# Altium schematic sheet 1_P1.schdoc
size 431 x 309 mm
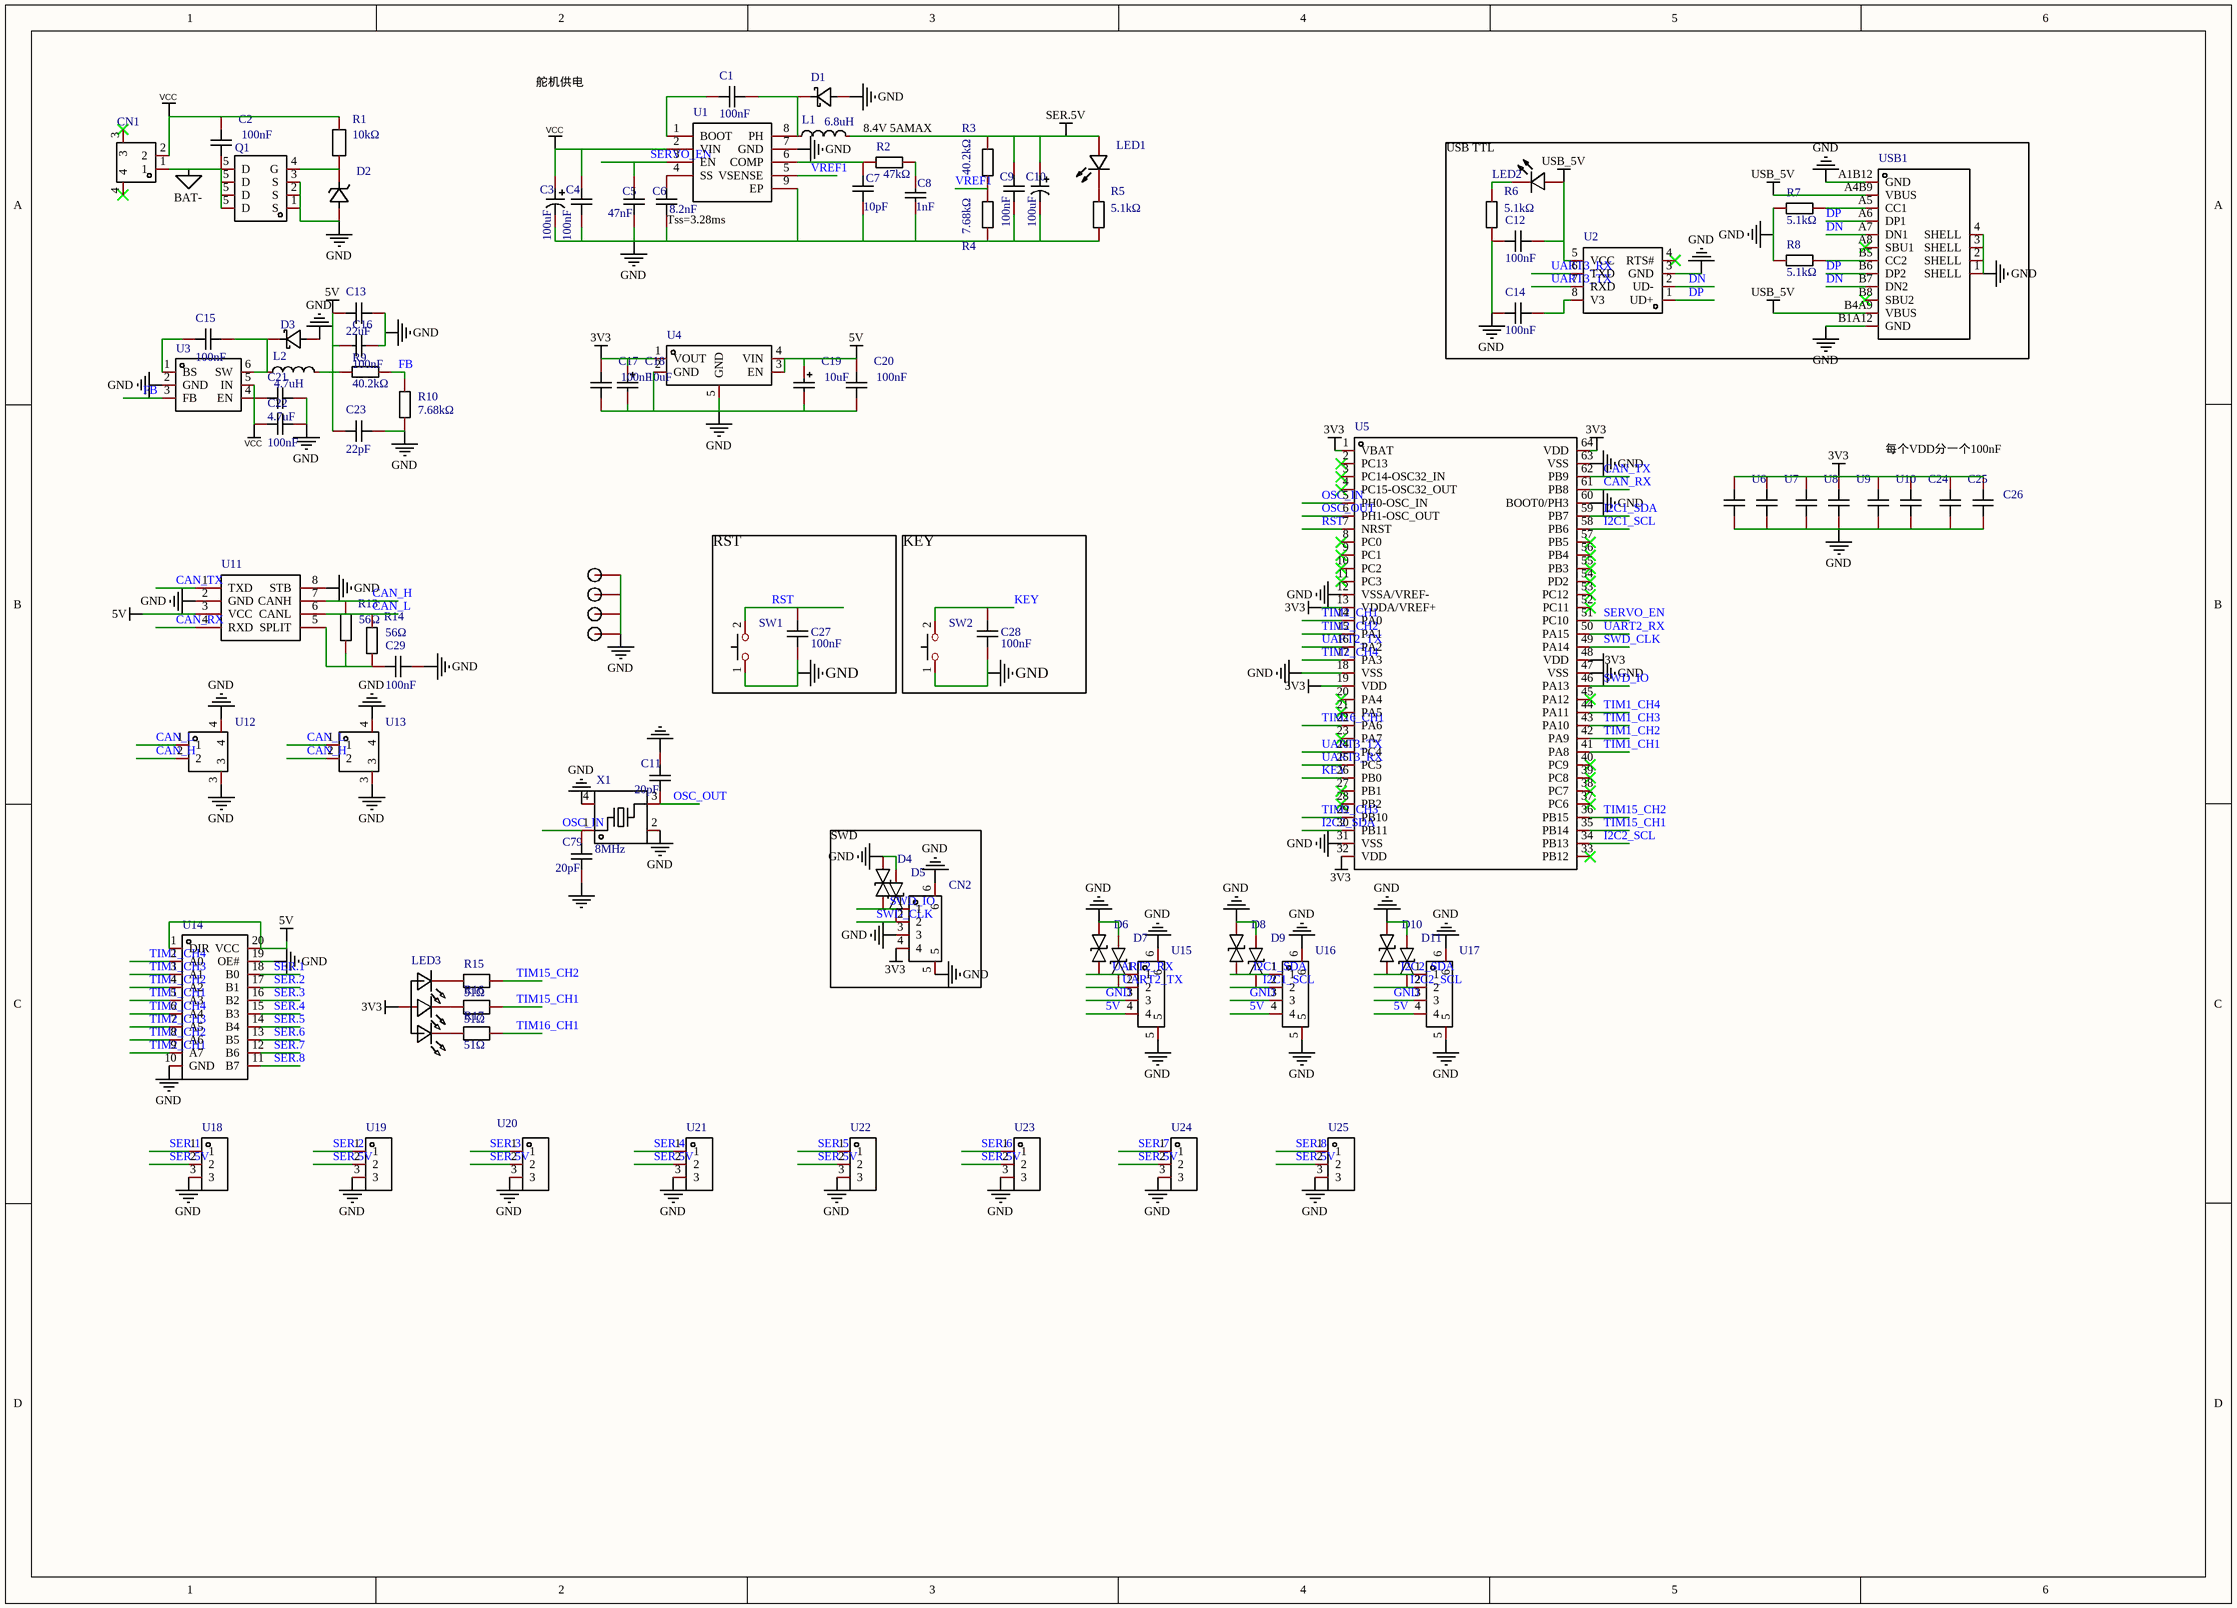
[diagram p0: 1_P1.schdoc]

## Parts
C1  value 100nF  [C0603]  (hidden comment: CC0603KRX7R9BB104)
C2  value 100nF  [C0603]  (hidden comment: CL10B104KC8NNNC)
C3  value 100uF  [CAP-SMD_BD6.3-L6.6-W6.6-LS7.2-FD]  (hidden comment: VT1E101M-CRE54)
C4  value 100nF  [C0603]  (hidden comment: CC0603KRX7R9BB104)
C5  value 47nF  [C0603]  (hidden comment: CL10B104KC8NNNC)
C6  value 8.2nF  [C0603]  (hidden comment: 0603B822J500CT)
C7  value 10pF  [C0603]  (hidden comment: CC0603GRNPO9BN100)
C8  value 1nF  [C0603]  (hidden comment: CL10B102KB8NNNC)
C9  value 100nF  [C0603]  (hidden comment: CC0603KRX7R9BB104)
C10  value 100uF  [CAP-SMD_BD6.3-L6.6-W6.6-LS7.2-FD]  (hidden comment: VT1E101M-CRE54)
C11  value 20pF  [C0603]  (hidden comment: 0603CG200G500NT)
C12  value 100nF  [C0603]  (hidden comment: TCC0603X7R104K500CT)
C13  value 22uF  [C0603]  (hidden comment: GRT188C80J226ME13D)
C14  value 100nF  [C0603]  (hidden comment: TCC0603X7R104K500CT)
C15  value 100nF  [C0603]  (hidden comment: CL10B104KC8NNNC)
C16  value 100nF  [C0402]  (hidden comment: GRM155R71E104KE14D)
C17  value 100nF  [C0402]  (hidden comment: CGA2B3X7R1V104MT0Y0F)
C18  value 10uF  [CAP-SMD_L3.5-W2.8-R-RD]  (hidden comment: TC211B106K025Y)
C19  value 10uF  [CAP-SMD_L3.5-W2.8-R-RD]  (hidden comment: TC211B106K025Y)
C20  value 100nF  [C0402]  (hidden comment: CGA2B3X7R1V104MT0Y0F)
C21  value 4.7uF  [C0603]  (hidden comment: GRM188C81E475KE11D)
C22  value 100nF  [C0603]  (hidden comment: CL10B104KC8NNNC)
C23  value 22pF  [C0603]  (hidden comment: GCM1885C2A220JA16D)
C24  0603  [C0603]  (value not drawn)
C25  0603  [C0603]  (value not drawn)
C26  0603  [C0603]  (value not drawn)
C27  Name: 100nF  [C0603]  (hidden comment: 1uF)
C28  Name: 100nF  [C0603]  (hidden comment: 1uF)
C29  value 100nF  [C0603]  (hidden comment: CL10B104KC8NNNC)
C79  value 20pF  [C0603]  (hidden comment: 0603CG200G500NT)
CN1  XT30PW-M  [CONN-TH_XT30PW-M]  (value not drawn)
CN2  X9821WVS-04-9TSN  [CONN-SMD_4P-P1.25_X9821WVS-04-9TSN]  (value not drawn)
D1  DSK310  [SOD-123_L2.7-W1.8-LS3.7-RD]  (value not drawn)
D2  ZMM9V1  [LL-34_L3.5-W1.5-RD]  (value not drawn)
D3  DSK310  [SOD-123_L2.7-W1.8-LS3.7-RD]  (value not drawn)
D4  PESD5V0L1BA  [SOD-323_L1.7-W1.3-LS2.5-BI]  (value not drawn)
D5  PESD5V0L1BA  [SOD-323_L1.7-W1.3-LS2.5-BI]  (value not drawn)
D6  PESD5V0L1BA  [SOD-323_L1.7-W1.3-LS2.5-BI]  (value not drawn)
D7  PESD5V0L1BA  [SOD-323_L1.7-W1.3-LS2.5-BI]  (value not drawn)
D8  PESD5V0L1BA  [SOD-323_L1.7-W1.3-LS2.5-BI]  (value not drawn)
D9  PESD5V0L1BA  [SOD-323_L1.7-W1.3-LS2.5-BI]  (value not drawn)
D10  PESD5V0L1BA  [SOD-323_L1.7-W1.3-LS2.5-BI]  (value not drawn)
D11  PESD5V0L1BA  [SOD-323_L1.7-W1.3-LS2.5-BI]  (value not drawn)
H1  M2.5_M2.5  [M2.5]  (value not drawn)
H2  M2.5_M2.5  [M2.5]  (value not drawn)
H3  M2.5_M2.5  [M2.5]  (value not drawn)
H4  M2.5_M2.5  [M2.5]  (value not drawn)
L1  value 6.8uH  [IND-SMD_L6.6-W6.6]  (hidden comment: SMMS0630-6R8M)
L2  value 4.7uH  [IND-SMD_L4.5-W4.0-1]  (hidden comment: MCS0420-4R7MPN2)
LED1  NCD0805R1  [LED0805-RD_RED]  (value not drawn)
LED2  NCD0805R1  [LED0805-RD_RED]  (value not drawn)
LED3  HL-PCF-3216S39FU70GH203BC-A  [LED-SMD_4P-L3.2-W1.5-BL]  (value not drawn)
Q1  WSD3066DN33  [DFN-8_L3.3-W3.3-P0.65-BL]  (value not drawn)
R1  value 10kΩ  [R0603]  (hidden comment: AR03BTD1002)
R2  value 47kΩ  [R0603]  (hidden comment: RS-03K473JT)
R3  value 40.2kΩ  [R0603]  (hidden comment: TC0325B4022T5E)
R4  value 7.68kΩ  [R0603]  (hidden comment: RMC06037.68K1%N)
R5  value 5.1kΩ  [R0603]  (hidden comment: RMC06035.1K1%N)
R6  value 5.1kΩ  [R0603]  (hidden comment: RMC06035.1K5%N)
R7  value 5.1kΩ  [R0603]  (hidden comment: RMC06035.1K1%N)
R8  value 5.1kΩ  [R0603]  (hidden comment: RMC06035.1K1%N)
R9  value 40.2kΩ  [R0603]  (hidden comment: TC0325B4022T5E)
R10  value 7.68kΩ  [R0603]  (hidden comment: RMC06037.68K1%N)
R13  value 56Ω  [R0603]  (hidden comment: CR0603JA0560G)
R14  value 56Ω  [R0603]  (hidden comment: CR0603JA0560G)
R15  value 51Ω  [R0603]  (hidden comment: ACPP0603 51R B)
R16  value 51Ω  [R0603]  (hidden comment: ACPP0603 51R B)
R17  value 51Ω  [R0603]  (hidden comment: ACPP0603 51R B)
SW1  YD-3410  [SW-SMD_L3.9-W2.9-LS4.8-EH-A]  (value not drawn)
SW2  YD-3410  [SW-SMD_L3.9-W2.9-LS4.8-EH-A]  (value not drawn)
U1  TPS54531DDAR  [SOIC-8_L5.0-W4.0-P1.27-LS6.0-BL-EP2.0]  (value not drawn)
U2  CH340N  [SOP-8_L4.9-W3.9-P1.27-LS6.0-BL]  (value not drawn)
U3  RY8411  [SOT-23-6_L2.9-W1.6-P0.95-LS2.8-TL]  (value not drawn)
U4  SK6019AD4-33  [XDFN-4_L1.0-W1.0-P0.65-BL-EP]  (value not drawn)
U5  STM32L431RCT6  [LQFP-64_L10.0-W10.0-P0.50-LS12.0-BL]  (value not drawn)
U6  CAP,MLCC,X7R,100nF,10V,10%,SMD0402,ROHS  [C0402]  (value not drawn)
U7  CAP,MLCC,X7R,100nF,10V,10%,SMD0402,ROHS  [C0402]  (value not drawn)
U8  CAP,MLCC,X7R,100nF,10V,10%,SMD0402,ROHS  [C0402]  (value not drawn)
U9  CAP,MLCC,X7R,100nF,10V,10%,SMD0402,ROHS  [C0402]  (value not drawn)
U10  CAP,MLCC,X7R,100nF,10V,10%,SMD0402,ROHS  [C0402]  (value not drawn)
U11  TJA1040T/CM,118  [SOIC-8_L5.0-W4.0-P1.27-LS6.0-BL]  (value not drawn)
U12  1.25-2PWTDK  [CONN-SMD_2P-P1.25_SHOU_1.25-2PWTDK]  (value not drawn)
U13  1.25-2PWTDK  [CONN-SMD_2P-P1.25_SHOU_1.25-2PWTDK]  (value not drawn)
U14  74HC245PW  [TSSOP-20_L6.5-W4.4-P0.65-LS6.4-BL]  (value not drawn)
U15  1.25-4PWTDK  [CONN-SMD_4P-P1.25_SHOUHAN_1.25-4PWTDK]  (value not drawn)
U16  1.25-4PWTDK  [CONN-SMD_4P-P1.25_SHOUHAN_1.25-4PWTDK]  (value not drawn)
U17  1.25-4PWTDK  [CONN-SMD_4P-P1.25_SHOUHAN_1.25-4PWTDK]  (value not drawn)
U18  3pin插件排针  [HDR-TH_3P-P2.00-V-M]  (value not drawn)
U19  3pin插件排针  [HDR-TH_3P-P2.00-V-M]  (value not drawn)
U20  3pin插件排针  [HDR-TH_3P-P2.00-V-M]  (value not drawn)
U21  3pin插件排针  [HDR-TH_3P-P2.00-V-M]  (value not drawn)
U22  3pin插件排针  [HDR-TH_3P-P2.00-V-M]  (value not drawn)
U23  3pin插件排针  [HDR-TH_3P-P2.00-V-M]  (value not drawn)
U24  3pin插件排针  [HDR-TH_3P-P2.00-V-M]  (value not drawn)
U25  3pin插件排针  [HDR-TH_3P-P2.00-V-M]  (value not drawn)
USB1  TYPE-C 16PIN 3MD(385)  [USB-C-SMD_TYPE-C16PIN]  (value not drawn)
X1  value 8MHz  [OSC-SMD_4P-L3.2-W2.5-BL]  (hidden comment: X32258MOB4SI)

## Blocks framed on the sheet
USB TTL: C12 C14 LED2 R6-R8 U2 USB1
RST: C27 SW1
KEY: C28 SW2
SWD: CN2 D4 D5

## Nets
3V3: C17.2 C18.1 C24.2 C25.2 C26.2 CN2.4 LED3.2 U4.1(VOUT) U5.1(VBAT) U5.13(VDDA/VREF+) U5.19(VDD) U5.32(VDD) U5.48(VDD) U5.64(VDD) U6.2 U7.2 U8.2 U9.2 U10.2
5V: C13.1 C16.1 C19.1 C20.2 C23.1 L2.2 R9.2 U4.3(EN) U4.4(VIN) U11.3(VCC) U14.1(DIR) U14.20(VCC) U15.4 U16.4 U17.4
BAT-: C2.1 CN1.1 Q1.5(D)
GND: C3.2 C4.1 C5.1 C6.1 C7.1 C8.1 C9.1 C10.2 C11.1 C12.1 C13.2 C14.1 C16.2 C17.1 C18.2 C19.2 C20.1 C21.2 C22.2 C23.2 C24.1 C25.1 C26.1 C27.1 C28.1 C29.2 C79.2 CN2.3 CN2.5 CN2.6 D1.2(A) D2.2(A) D3.2(A) D4.2 D5.2 D6.2 D7.2 D8.2 D9.2 D10.2 D11.2 H1.1 H2.1 H3.1 H4.1 Q1.1(S) Q1.2(S) Q1.3(S) R4.1 R5.1 R6.1 R7.1 R8.1 R10.1 SW1.1 SW2.1 U1.7(GND) U1.9(EP) U2.3(GND) U3.2(GND) U4.2(GND) U4.5(GND) U5.12(VSSA/VREF-) U5.18(VSS) U5.31(VSS) U5.47(VSS) U5.60(BOOT0/PH3) U5.63(VSS) U6.1 U7.1 U8.1 U9.1 U10.1 U11.2(GND) U11.8(STB) U12.3 U12.4 U13.3 U13.4 U14.10(GND) U14.19(OE#) U15.3 U15.5 U15.6 U16.3 U16.5 U16.6 U17.3 U17.5 U17.6 U18.3 U19.3 U20.3 U21.3 U22.3 U23.3 U24.3 U25.3 USB1.1(SHELL) USB1.2(SHELL) USB1.3(SHELL) USB1.4(SHELL) USB1.A1B12(GND) USB1.B1A12(GND) X1.2(GND) X1.4(GND)
SER.5V: C9.2 C10.1 L1.2 LED1.2(+) R3.2 U18.2 U19.2 U20.2 U21.2 U22.2 U23.2 U24.2 U25.2
USB_5V: C12.2 LED2.2(+) U2.5(VCC) USB1.A4B9(VBUS) USB1.B4A9(VBUS)
VCC: C2.2 C3.1 C4.2 C21.1 C22.1 CN1.2 R1.2 U1.2(VIN) U3.4(EN) U3.5(IN)
CAN_H: R13.2 U11.7(CANH) U12.2 U13.2
CAN_L: R14.2 U11.6(CANL) U12.1 U13.1
CAN_RX: U5.61(PB8) U11.4(RXD)
CAN_TX: U5.62(PB9) U11.1(TXD)
DN: U2.2(UD-) USB1.A7(DN1) USB1.B7(DN2)
DP: U2.1(UD+) USB1.A6(DP1) USB1.B6(DP2)
FB: R9.1 R10.2 U3.3(FB)
I2C1_SCL: D9.1 U5.58(PB6) U16.2
I2C1_SDA: D8.1 U5.59(PB7) U16.1
I2C2_SCL: D11.1 U5.34(PB13) U17.2
I2C2_SDA: D10.1 U5.30(PB11) U17.1
KEY: C28.2 SW2.2 U5.26(PB0)
OSC_IN: C79.1 U5.5(PH0-OSC_IN) X1.1
OSC_OUT: C11.2 U5.6(PH1-OSC_OUT) X1.3
RST: C27.2 SW1.2 U5.7(NRST)
SER.1: U14.18(B0) U18.1
SER.2: U14.17(B1) U19.1
SER.3: U14.16(B2) U20.1
SER.4: U14.15(B3) U21.1
SER.5: U14.14(B4) U22.1
SER.6: U14.13(B5) U23.1
SER.7: U14.12(B6) U24.1
SER.8: U14.11(B7) U25.1
SERVO_EN: C5.2 U1.3(EN) U5.51(PC10)
SWD_CLK: CN2.2 D5.1 U5.49(PA14)
SWD_IO: CN2.1 D4.1 U5.46(PA13)
TIM1_CH1: U5.41(PA8) U14.5(A3)
TIM1_CH2: U5.42(PA9) U14.4(A2)
TIM1_CH3: U5.43(PA10) U14.3(A1)
TIM1_CH4: U5.44(PA11) U14.2(A0)
TIM2_CH1: U5.14(PA0) U14.9(A7)
TIM2_CH2: U5.15(PA1) U14.8(A6)
TIM2_CH3: U5.29(PB10) U14.7(A5)
TIM2_CH4: U5.17(PA3) U14.6(A4)
TIM15_CH1: R16.2 U5.35(PB14)
TIM15_CH2: R15.2 U5.36(PB15)
TIM16_CH1: R17.2 U5.22(PA6)
UART2_RX: D6.1 U5.50(PA15) U15.1
UART2_TX: D7.1 U5.16(PA2) U15.2
UART3_RX: U2.6(TXD) U5.25(PC5)
UART3_TX: U2.7(RXD) U5.24(PC4)
VREF1: R3.1 R4.2 U1.5(VSENSE)
NetC1_1: C1.1 U1.1(BOOT)
NetC1_2: C1.2 D1.1(K) L1.1 U1.8(PH)
NetC6_2: C6.2 U1.4(SS)
NetC7_2: C7.2 R2.1 U1.6(COMP)
NetC8_2: C8.2 R2.2
NetC14_2: C14.2 U2.8(V3)
NetC15_1: C15.1 U3.1(BS)
NetC15_2: C15.2 D3.1(K) L2.1 U3.6(SW)
NetC29_1: C29.1 R13.1 R14.1 U11.5(SPLIT)
NetD2_1: D2.1(K) Q1.4(G) R1.1
NetLED1_1: LED1.1(-) R5.2
NetLED2_1: LED2.1(-) R6.2
NetLED3_1: LED3.1 R15.1
NetLED3_3: LED3.3 R16.1
NetLED3_4: LED3.4 R17.1
NetR7_2: R7.2 USB1.A5(CC1)
NetR8_2: R8.2 USB1.B5(CC2)

Not connected (* = marked no-connect by the designer): CN1 3* 4*; U2 4(RTS#)*; U5 2(PC13)* 3(PC14-OSC32_IN)* 4(PC15-OSC32_OUT)* 8(PC0)* 9(PC1)* 10(PC2)* 11(PC3)* 20(PA4)* 21(PA5)* 23(PA7)* 27(PB1)* 28(PB2)* 33(PB12)* 37(PC6)* 38(PC7)* 39(PC8)* 40(PC9)* 45(PA12)* 52(PC11)* 53(PC12)* 54(PD2)* 55(PB3)* 56(PB4)* 57(PB5)*; USB1 A8(SBU1)* B8(SBU2)*

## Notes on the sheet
- 舵机供电
- 8.4V 5AMAX
- (near C6) Tss=3.28ms
- 每个VDD分一个100nF

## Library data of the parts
C1 C4 C9 = CC0603KRX7R9BB104: 容值:100nF;精度:±10%;额定电压:50V;温度系数:X7R;; Manufacturer: YAGEO(国巨); Add into BOM: yes; Tolerance: ±10%; Voltage Rated: 50V; Temperature Coefficient: X7R
C2 C5 C15 C22 C29 = CL10B104KC8NNNC: 容值:100nF;精度:±10%;额定电压:100V;温度系数:X7R;; Manufacturer: SAMSUNG(三星); Add into BOM: yes; Tolerance: ±10%; Voltage Rated: 100V; Temperature Coefficient: X7R
C3 C10 = VT1E101M-CRE54: 容值:100uF;精度:-;额定电压:25V;; Manufacturer: VT(首科); Add into BOM: yes; Rated Voltage: 25V
C6 = 0603B822J500CT: 容值:8.2nF;精度:±5%;额定电压:50V;温度系数:X7R;; Manufacturer: 华新科(Walsin); Add into BOM: yes; Tolerance: ±5%; Voltage Rated: 50V; Temperature Coefficient: X7R
C7 = CC0603GRNPO9BN100: 容值:10pF;精度:±2%;额定电压:50V;温度系数:NP0;; Manufacturer: YAGEO(国巨); Add into BOM: yes; Tolerance: ±2%; Voltage Rated: 50V; Temperature Coefficient: NP0
C8 = CL10B102KB8NNNC: 容值:1nF;精度:±10%;额定电压:50V;温度系数:X7R;; Manufacturer: SAMSUNG(三星); Add into BOM: yes; Tolerance: ±10%; Voltage Rated: 50V; Temperature Coefficient: X7R
C11 C79 = 0603CG200G500NT: 容值:20pF;精度:±2%;额定电压:50V;温度系数:C0G;; Manufacturer: FH(风华); Add into BOM: yes; Tolerance: ±2%; Voltage Rated: 50V; Temperature Coefficient: C0G
C12 C14 = TCC0603X7R104K500CT: 容值:100nF;精度:±10%;额定电压:50V;温度系数:X7R;; Manufacturer: CCTC(三环); Add into BOM: yes; Tolerance: ±10%; Voltage Rated: 50V; Temperature Coefficient: X7R
C13 = GRT188C80J226ME13D: 容值:22uF;精度:±20%;额定电压:-;温度系数:-;; Manufacturer: muRata(村田); Add into BOM: yes; Tolerance: ±20%
C16 = GRM155R71E104KE14D: 容值:100nF;精度:±10%;额定电压:25V;温度系数:X7R;; Manufacturer: muRata(村田); Add into BOM: yes; Tolerance: ±10%; Voltage Rated: 25V; Temperature Coefficient: X7R
C17 C20 = CGA2B3X7R1V104MT0Y0F: 容值:100nF;精度:±20%;额定电压:35V;温度系数:X7R;; Manufacturer: TDK; Add into BOM: yes; Tolerance: ±20%; Voltage Rated: 35V; Temperature Coefficient: X7R
C18 C19 = TC211B106K025Y: 容值:10uF;精度:±10%;额定电压:25V;等效串联电阻:3Ω@100kHz;工作温度:-55~+125;; Manufacturer: Sunlord(顺络); Add into BOM: yes; Tolerance: ±10%; Rated Voltage: 25V
C21 = GRM188C81E475KE11D: 容值:4.7uF;精度:±10%;额定电压:-;温度系数:-;; Manufacturer: muRata(村田); Add into BOM: yes; Tolerance: ±10%
C23 = GCM1885C2A220JA16D: 容值:22pF;精度:±5%;额定电压:100V;温度系数:C0G;; Manufacturer: muRata(村田); Add into BOM: yes; Tolerance: ±5%; Voltage Rated: 100V; Temperature Coefficient: C0G
C24-C26 = 0603: Symbol: 0603_C9900021180; Add into BOM: yes
C27 C28 = 1uF: Manufacturer: YAGEO; Manufacturer Part: CC0603JRNPO0BN200; Convert to PCB: yes
CN1 = XT30PW-M: Socket,DCsupply,XT30,male,PIN:2; Manufacturer: AMASS(艾迈斯); Add into BOM: yes
CN2 = X9821WVS-04-9TSN: 参考系列:-;间距:1.25mm;插针结构:1x4P;排数:1;每排PIN数:4;行距:-;安装方式:-;触头材质:黄铜;; Manufacturer: XKB Connectivity(中国星坤); Add into BOM: yes; Pitch: 1.25mm; Pins Structure: 1x4P; Number of PINs Per Row: 4
D1 D3 = DSK310: 二极管配置:-;直流反向耐压(Vr):100V;平均整流电流(Io):3A;正向压降(Vf):850mV@3A;反向电流(Ir):500A@100V;; Manufacturer: LGE(鲁光); Symbol: DSK310_C713648; Add into BOM: yes; Reverse Voltage (Vr): 100V; Average Rectified Current (Io): 3A
D2 = ZMM9V1: 稳压值(标称值):-;精度:-;功率:500mW;反向电流(Ir):100nA@6.8V;; Manufacturer: Slkor(萨科微); Symbol: ZMM9V1_C707200; Add into BOM: yes; Power Dissipation: 500mW
D4-D11 = PESD5V0L1BA: 极性:-;反向关断电压（典型值）:-;击穿电压（最小值）:-;箝位电压:-;峰值脉冲电流（10/1000us）:-;; Manufacturer: TECH PUBLIC(台舟); Symbol: PESD5V0L1BA_C2827691; Add into BOM: yes
H1-H4 = M2.5_M2.5: Convert to PCB: yes
L1 = SMMS0630-6R8M: 电感值:6.8uH;精度:±20%;额定电流:-;直流电阻(DCR):-;; Manufacturer: SXN(顺翔诺); Add into BOM: yes; Tolerance: ±20%
L2 = MCS0420-4R7MPN2: 电感值:4.7uH;精度:±20%;额定电流:2.2A;饱和电流(Isat):3.5A;直流电阻(DCR):98mΩ;; Manufacturer: PSA(信昌电陶); Add into BOM: yes; Tolerance: ±20%; Rated Current: 2.2A; Saturation Current (Isat): 3.5A; DC Resistance (DCR): 98mΩ
LED1 LED2 = NCD0805R1: 发光颜色:红灯;; Manufacturer: 国星光电; Symbol: FC-2012HRK-620D; Add into BOM: yes; Emitted Color: 红灯
LED3 = HL-PCF-3216S39FU70GH203BC-A: 发光颜色:RGB三色;透镜颜色:无色透明;主波长:-;色温:-;光通量(25时):-;测试电流:20mA;正向电压(VF):2.4V；3.4V；3.4V;发光强度:350mcd；1000mcd；220mcd;功率:102mW；102mW；72mW;发光角度:140°;安装方式:正贴;工作温度:-40~+85;; Manufacturer: HONGLITRONIC(鸿利光电); Add into BOM: yes; Emitted Color: RGB三色; Lens Color: 无色透明; Forward Current: 20mA; Viewing Angle: 140°; Mounting Sytle: 正贴
Q1 = WSD3066DN33: 类型:N沟道;漏源电压(Vdss):30V;连续漏极电流(Id):50A;功率(Pd):45W;导通电阻(RDS(on)@Vgs,Id):5.7mΩ@10V,35A;阈值电压(Vgs(th)@Id):2.5V@250A;; Manufacturer: WINSOK微硕; Add into BOM: yes; Type: N沟道; Drain Source Voltage (Vdss): 30V; Continuous Drain Current (Id): 50A; Power Dissipation (Pd): 45W
R1 = AR03BTD1002: 阻值:10kΩ;精度:±0.01%;功率:-;温度系数:±50ppm/;最大工作电压:50V;工作温度范围:-55~+125;; Manufacturer: Viking(光颉); Add into BOM: yes; Tolerance: ±0.01%; Temperature Coefficient: ±50ppm/; Overload Voltage (Max): 50V
R2 = RS-03K473JT: 阻值:47kΩ;精度:±5%;功率:100mW;温度系数:±100ppm/;最大工作电压:50V;工作温度范围:-55~+155;; Manufacturer: FH(风华); Add into BOM: yes; Tolerance: ±5%; Power(Watts): 100mW; Overload Voltage (Max): 50V
R3 R9 = TC0325B4022T5E: 阻值:40.2kΩ;精度:±0.1%;功率:1/6W;温度系数:±25ppm/;最大工作电压:75V;工作温度范围:-55~+155;; Manufacturer: UNI-ROYAL(厚声); Add into BOM: yes; Tolerance: ±0.1%; Power(Watts): 1/6W; Temperature Coefficient: ±25ppm/; Overload Voltage (Max): 75V
R4 R10 = RMC06037.68K1%N: 阻值:7.68kΩ;精度:±1%;功率:0.1W;; Manufacturer: Tyohm(幸亚电阻); Add into BOM: yes; Tolerance: ±1%; Power(Watts): 0.1W
R5 R7 R8 = RMC06035.1K1%N: 阻值:5.1kΩ;精度:±1%;功率:0.1W;; Manufacturer: Tyohm(幸亚电阻); Add into BOM: yes; Tolerance: ±1%; Power(Watts): 0.1W
R6 = RMC06035.1K5%N: 阻值:5.1kΩ;精度:±5%;功率:0.1W;; Manufacturer: Tyohm(幸亚电阻); Add into BOM: yes; Tolerance: ±5%; Power(Watts): 0.1W
R13 R14 = CR0603JA0560G: 电阻类型:厚膜电阻;阻值:56Ω;精度:±5%;功率:1/10W;温度系数:±200ppm/;最大工作电压:50V;工作温度范围:-55~+125;; Manufacturer: LIZ(丽智电子); Add into BOM: yes; Tolerance: ±5%; Power(Watts): 1/10W; Overload Voltage (Max): 50V
R15-R17 = ACPP0603 51R B: 电阻类型:薄膜电阻;阻值:51Ω;精度:±0.1%;功率:62.5mW;温度系数:-;最大工作电压:50V;工作温度范围:-55~+150;; Manufacturer: Ohmite; Add into BOM: yes; Tolerance: ±0.1%; Power(Watts): 62.5mW; Overload Voltage (Max): 50V
SW1 SW2 = YD-3410: Add into BOM: yes
U1 = TPS54531DDAR: 功能类型:降压型;同步整流:-;输出通道数:-;拓扑结构:-;输入电压:-;输出电流(最大值):-;开关频率:-;; Manufacturer: TI(德州仪器); Add into BOM: yes; Function: 降压型
U2 = CH340N: Manufacturer: WCH(南京沁恒); Symbol: CH340N_C2977777; Add into BOM: yes
U3 = RY8411: Manufacturer: RYCHiP(蕊源); Symbol: RY8411_C2935411; Add into BOM: yes
U4 = SK6019AD4-33: 输出类型:-;; Manufacturer: 洺太电子(suntek); Add into BOM: yes
U5 = STM32L431RCT6: 主频（MAX):80MHz;工作电压:1.71V ~ 3.6V;; Manufacturer: ST(意法半导体); Add into BOM: yes; Speed: 80MHz; Program Memory Size: 256KB; RAM Size: 64KB; Number of I/O: 52; A/D: 16x12bit; D/A: 2x12bit; PWM: 1; UART/USART: 3 USART+1 UART; SPI: 3
U6-U10 = CAP,MLCC,X7R,100nF,10V,10%,SMD0402,ROHS: Add into BOM: yes
U11 = TJA1040T/CM,118: 类型:收发器;协议类别:CAN总线;; Manufacturer: NXP(恩智浦); Add into BOM: yes; Protocol: CAN总线; Supply Voltage: 4.75V ~ 5.25V
U12 U13 = 1.25-2PWTDK: 间距:1.25mm;插针结构:1x2P;排数:1;每排PIN数:2;公母:公型插针;安装方式:卧贴;额定电流:1A;工作温度范围:-25~+85;; Manufacturer: SHOU HAN(首韩); Add into BOM: yes; Pitch: 1.25mm; Pins Structure: 1x2P; Number of PINs Per Row: 2; Gender: 公型插针; Current Rating (Max): 1A
U14 = 74HC245PW: 逻辑电路的归属系列:-;逻辑类型:-;元件数:-;每元件位数:-;; Add into BOM: yes
U15-U17 = 1.25-4PWTDK: 间距:1.25mm;插针结构:1x4P;排数:1;每排PIN数:4;公母:公型插针;安装方式:卧贴;额定电流:1A;工作温度范围:-25~+85;; Manufacturer: SHOU HAN(首韩); Add into BOM: yes; Pitch: 1.25mm; Pins Structure: 1x4P; Number of PINs Per Row: 4; Gender: 公型插针; Current Rating (Max): 1A
U18-U25 = 3pin插件排针: Add into BOM: yes
USB1 = TYPE-C 16PIN 3MD(385): 连接器类型:Type-C;标准:-;公母:母座;触点数量:16;端口数量:1;安装方式:卧贴;额定电流 - 电源:3A;工作温度范围:-40~+85;; Manufacturer: SHOU HAN(首韩); Add into BOM: yes; Gender: 母座; Number of Contacts: 16; Number of Ports: 1; Current Rating - Power (Max): 3A
X1 = X32258MOB4SI: 晶振类型:贴片无源晶振;频率:8MHz;频率公差:±10ppm;频率稳定度:±30ppm;负载电容:12pF;工作温度:-40~+85;; Manufacturer: YXC扬兴科技; Add into BOM: yes; Crystal Type: 贴片无源晶振; Frequency Tolerance: ±10ppm; Frequency Stability: ±30ppm; Load Capacitance: 12pF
